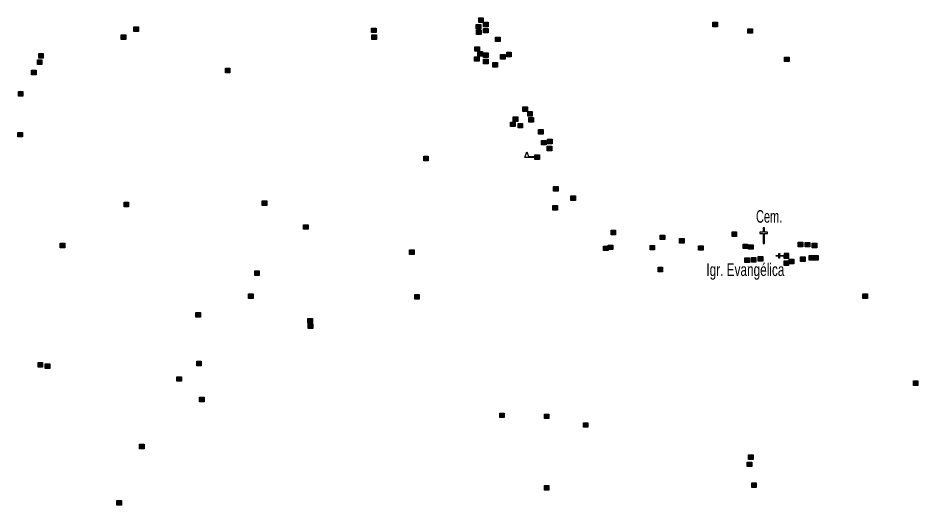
# Model space of a CAD drawing. Extents: x 647.8 to 672.9, y 6929.3 to 6957.3.
# Drawn here: x 654.32 to 660.04, y 6953.98 to 6957.07 of the extents above; entities that cross this region are included whole.
import ezdxf
from ezdxf.enums import TextEntityAlignment as Align

# ---------------------------------------------------------------- set-up
doc = ezdxf.new("R2010")
doc.units = 0
doc.header["$LTSCALE"] = 0.032
for name, color, linetype, lineweight in [('2', 7, 'Continuous', 25), ('20', 7, 'Continuous', 25), ('4', 7, 'Continuous', 25), ('6', 7, 'Continuous', 25)]:
    doc.layers.add(name, color=color, linetype=linetype, lineweight=lineweight)
doc.layers.add('61', color=7, linetype='Continuous')

msp = doc.modelspace()

# ---------------------------------------------------------------- hatches: boundary and pattern name
at = {"layer": '2'}
for points in [[(657.2334, 6957.0283), (657.2624, 6957.0283), (657.2624, 6956.9993), (657.2334, 6956.9993)], [(657.2488, 6957.07), (657.2778, 6957.07), (657.2778, 6957.041), (657.2488, 6957.041)], [(657.2795, 6957.0436), (657.3085, 6957.0436), (657.3085, 6957.0146), (657.2795, 6957.0146)], [(658.7362, 6957.0436), (658.7652, 6957.0436), (658.7652, 6957.0146), (658.7362, 6957.0146)], [(655.0593, 6957.0129), (655.0883, 6957.0129), (655.0883, 6956.9839), (655.0593, 6956.9839)], [(656.5687, 6957.0063), (656.5977, 6957.0063), (656.5977, 6956.9773), (656.5687, 6956.9773)], [(657.2356, 6956.9932), (657.2646, 6956.9932), (657.2646, 6956.9642), (657.2356, 6956.9642)], [(657.2795, 6957.0041), (657.3085, 6957.0041), (657.3085, 6956.9751), (657.2795, 6956.9751)], [(658.9578, 6957.002), (658.9868, 6957.002), (658.9868, 6956.973), (658.9578, 6956.973)], [(654.9803, 6956.9625), (655.0093, 6956.9625), (655.0093, 6956.9335), (654.9803, 6956.9335)], [(656.5709, 6956.9625), (656.5999, 6956.9625), (656.5999, 6956.9335), (656.5709, 6956.9335)], [(657.3563, 6956.9493), (657.3853, 6956.9493), (657.3853, 6956.9203), (657.3563, 6956.9203)], [(657.2246, 6956.8879), (657.2536, 6956.8879), (657.2536, 6956.8589), (657.2246, 6956.8589)], [(657.2444, 6956.8572), (657.2734, 6956.8572), (657.2734, 6956.8282), (657.2444, 6956.8282)], [(657.4265, 6956.8528), (657.4555, 6956.8528), (657.4555, 6956.8238), (657.4265, 6956.8238)], [(654.4472, 6956.8045), (654.4762, 6956.8045), (654.4762, 6956.7755), (654.4472, 6956.7755)], [(654.456, 6956.844), (654.485, 6956.844), (654.485, 6956.815), (654.456, 6956.815)], [(657.2225, 6956.8243), (657.2515, 6956.8243), (657.2515, 6956.7953), (657.2225, 6956.7953)], [(657.2795, 6956.8484), (657.3085, 6956.8484), (657.3085, 6956.8194), (657.2795, 6956.8194)], [(657.2795, 6956.8089), (657.3085, 6956.8089), (657.3085, 6956.7799), (657.2795, 6956.7799)], [(657.387, 6956.8374), (657.416, 6956.8374), (657.416, 6956.8084), (657.387, 6956.8084)], [(659.1903, 6956.8221), (659.2193, 6956.8221), (659.2193, 6956.7931), (659.1903, 6956.7931)], [(654.4099, 6956.7387), (654.4389, 6956.7387), (654.4389, 6956.7097), (654.4099, 6956.7097)], [(655.6407, 6956.7519), (655.6697, 6956.7519), (655.6697, 6956.7229), (655.6407, 6956.7229)], [(657.3387, 6956.787), (657.3677, 6956.787), (657.3677, 6956.758), (657.3387, 6956.758)], [(654.3266, 6956.6027), (654.3556, 6956.6027), (654.3556, 6956.5737), (654.3266, 6956.5737)], [(657.5296, 6956.5061), (657.5586, 6956.5061), (657.5586, 6956.4771), (657.5296, 6956.4771)], [(657.5603, 6956.4754), (657.5893, 6956.4754), (657.5893, 6956.4464), (657.5603, 6956.4464)], [(657.4506, 6956.4096), (657.4796, 6956.4096), (657.4796, 6956.3806), (657.4506, 6956.3806)], [(657.4682, 6956.4425), (657.4972, 6956.4425), (657.4972, 6956.4135), (657.4682, 6956.4135)], [(657.4989, 6956.4008), (657.5279, 6956.4008), (657.5279, 6956.3718), (657.4989, 6956.3718)], [(657.5669, 6956.4381), (657.5959, 6956.4381), (657.5959, 6956.4091), (657.5669, 6956.4091)], [(654.3244, 6956.3438), (654.3534, 6956.3438), (654.3534, 6956.3148), (654.3244, 6956.3148)], [(657.6283, 6956.3614), (657.6573, 6956.3614), (657.6573, 6956.3324), (657.6283, 6956.3324)], [(657.6481, 6956.2933), (657.6771, 6956.2933), (657.6771, 6956.2643), (657.6481, 6956.2643)], [(657.6854, 6956.2999), (657.7144, 6956.2999), (657.7144, 6956.2709), (657.6854, 6956.2709)], [(657.6832, 6956.256), (657.7122, 6956.256), (657.7122, 6956.227), (657.6832, 6956.227)], [(656.9, 6956.1924), (656.929, 6956.1924), (656.929, 6956.1634), (656.9, 6956.1634)], [(657.7248, 6955.9994), (657.7538, 6955.9994), (657.7538, 6955.9704), (657.7248, 6955.9704)], [(657.8345, 6955.9401), (657.8635, 6955.9401), (657.8635, 6955.9111), (657.8345, 6955.9111)], [(654.9979, 6955.9006), (655.0269, 6955.9006), (655.0269, 6955.8716), (654.9979, 6955.8716)], [(655.8754, 6955.9094), (655.9044, 6955.9094), (655.9044, 6955.8804), (655.8754, 6955.8804)], [(657.7205, 6955.8787), (657.7495, 6955.8787), (657.7495, 6955.8497), (657.7205, 6955.8497)], [(656.1365, 6955.758), (656.1655, 6955.758), (656.1655, 6955.729), (656.1365, 6955.729)], [(658.089, 6955.7229), (658.118, 6955.7229), (658.118, 6955.6939), (658.089, 6955.6939)], [(658.8569, 6955.712), (658.8859, 6955.712), (658.8859, 6955.683), (658.8569, 6955.683)], [(658.4005, 6955.6922), (658.4295, 6955.6922), (658.4295, 6955.6632), (658.4005, 6955.6632)], [(658.5234, 6955.6703), (658.5524, 6955.6703), (658.5524, 6955.6413), (658.5234, 6955.6413)], [(654.592, 6955.6396), (654.621, 6955.6396), (654.621, 6955.6106), (654.592, 6955.6106)], [(656.81, 6955.5979), (656.839, 6955.5979), (656.839, 6955.5689), (656.81, 6955.5689)], [(658.0408, 6955.622), (658.0698, 6955.622), (658.0698, 6955.593), (658.0408, 6955.593)], [(658.0715, 6955.6286), (658.1005, 6955.6286), (658.1005, 6955.5996), (658.0715, 6955.5996)], [(658.3369, 6955.6264), (658.3659, 6955.6264), (658.3659, 6955.5974), (658.3369, 6955.5974)], [(658.6441, 6955.6242), (658.6731, 6955.6242), (658.6731, 6955.5952), (658.6441, 6955.5952)], [(658.9271, 6955.6352), (658.9561, 6955.6352), (658.9561, 6955.6062), (658.9271, 6955.6062)], [(658.9622, 6955.6308), (658.9912, 6955.6308), (658.9912, 6955.6018), (658.9622, 6955.6018)], [(659.2774, 6955.6465), (659.3064, 6955.6465), (659.3064, 6955.6175), (659.2774, 6955.6175)], [(659.322, 6955.6456), (659.351, 6955.6456), (659.351, 6955.6166), (659.322, 6955.6166)], [(659.3656, 6955.6396), (659.3946, 6955.6396), (659.3946, 6955.6106), (659.3656, 6955.6106)], [(658.938, 6955.5474), (658.967, 6955.5474), (658.967, 6955.5184), (658.938, 6955.5184)], [(658.9797, 6955.5496), (659.0087, 6955.5496), (659.0087, 6955.5206), (658.9797, 6955.5206)], [(659.0236, 6955.5562), (659.0526, 6955.5562), (659.0526, 6955.5272), (659.0236, 6955.5272)], [(659.2208, 6955.5393), (659.2498, 6955.5393), (659.2498, 6955.5103), (659.2208, 6955.5103)], [(659.2913, 6955.5535), (659.3203, 6955.5535), (659.3203, 6955.5245), (659.2913, 6955.5245)], [(659.3475, 6955.5626), (659.3765, 6955.5626), (659.3765, 6955.5336), (659.3475, 6955.5336)], [(659.3752, 6955.5617), (659.4042, 6955.5617), (659.4042, 6955.5327), (659.3752, 6955.5327)], [(658.3874, 6955.4882), (658.4164, 6955.4882), (658.4164, 6955.4592), (658.3874, 6955.4592)], [(659.1875, 6955.5285), (659.2165, 6955.5285), (659.2165, 6955.4995), (659.1875, 6955.4995)], [(655.8272, 6955.4641), (655.8562, 6955.4641), (655.8562, 6955.4351), (655.8272, 6955.4351)], [(655.7877, 6955.3193), (655.8167, 6955.3193), (655.8167, 6955.2903), (655.7877, 6955.2903)], [(656.8429, 6955.3149), (656.8719, 6955.3149), (656.8719, 6955.2859), (656.8429, 6955.2859)], [(659.6883, 6955.3193), (659.7173, 6955.3193), (659.7173, 6955.2903), (659.6883, 6955.2903)], [(655.4542, 6955.2008), (655.4832, 6955.2008), (655.4832, 6955.1718), (655.4542, 6955.1718)], [(656.165, 6955.1613), (656.194, 6955.1613), (656.194, 6955.1323), (656.165, 6955.1323)], [(656.1672, 6955.1284), (656.1962, 6955.1284), (656.1962, 6955.0994), (656.1672, 6955.0994)], [(654.4516, 6954.8827), (654.4806, 6954.8827), (654.4806, 6954.8537), (654.4516, 6954.8537)], [(654.4977, 6954.8739), (654.5267, 6954.8739), (654.5267, 6954.8449), (654.4977, 6954.8449)], [(655.4586, 6954.8915), (655.4876, 6954.8915), (655.4876, 6954.8625), (655.4586, 6954.8625)], [(655.3336, 6954.7928), (655.3626, 6954.7928), (655.3626, 6954.7638), (655.3336, 6954.7638)], [(660.0086, 6954.7664), (660.0376, 6954.7664), (660.0376, 6954.7374), (660.0086, 6954.7374)], [(655.4762, 6954.6633), (655.5052, 6954.6633), (655.5052, 6954.6343), (655.4762, 6954.6343)], [(657.3826, 6954.5624), (657.4116, 6954.5624), (657.4116, 6954.5334), (657.3826, 6954.5334)], [(657.6656, 6954.5558), (657.6946, 6954.5558), (657.6946, 6954.5268), (657.6656, 6954.5268)], [(657.9135, 6954.501), (657.9425, 6954.501), (657.9425, 6954.472), (657.9135, 6954.472)], [(655.0966, 6954.365), (655.1256, 6954.365), (655.1256, 6954.336), (655.0966, 6954.336)], [(655.0966, 6954.365), (655.1256, 6954.365), (655.1256, 6954.336), (655.0966, 6954.336)], [(658.9622, 6954.2969), (658.9912, 6954.2969), (658.9912, 6954.2679), (658.9622, 6954.2679)], [(658.9534, 6954.2509), (658.9824, 6954.2509), (658.9824, 6954.2219), (658.9534, 6954.2219)], [(658.9819, 6954.1192), (659.0109, 6954.1192), (659.0109, 6954.0902), (658.9819, 6954.0902)], [(657.6656, 6954.1017), (657.6946, 6954.1017), (657.6946, 6954.0727), (657.6656, 6954.0727)], [(654.9518, 6954.0074), (654.9808, 6954.0074), (654.9808, 6953.9784), (654.9518, 6953.9784)]]:
    msp.add_hatch(color=256, dxfattribs=at).paths.add_polyline_path(points)
at = {"layer": '4'}
msp.add_hatch(color=256, dxfattribs=at).paths.add_polyline_path([(657.6348, 6956.1723), (657.6048, 6956.1724), (657.605, 6956.2024), (657.635, 6956.2023)])
at = {"layer": '6'}
for points in [[(659.1869, 6955.5623), (659.1868, 6955.5573), (659.1593, 6955.5575), (659.1592, 6955.545), (659.1542, 6955.5451), (659.1543, 6955.5576), (659.1368, 6955.5578), (659.1369, 6955.5627), (659.1544, 6955.5626), (659.1544, 6955.5751), (659.1595, 6955.575), (659.1594, 6955.5625)], [(659.1868, 6955.5449), (659.2168, 6955.5446), (659.217, 6955.5746), (659.187, 6955.5748)]]:
    msp.add_hatch(color=256, dxfattribs=at).paths.add_polyline_path(points)

# ---------------------------------------------------------------- linework, layer by layer
at = {"layer": '2'}
for points in [[(657.2334, 6957.0283), (657.2624, 6957.0283), (657.2624, 6956.9993), (657.2334, 6956.9993)], [(657.2488, 6957.07), (657.2778, 6957.07), (657.2778, 6957.041), (657.2488, 6957.041)], [(657.2795, 6957.0436), (657.3085, 6957.0436), (657.3085, 6957.0146), (657.2795, 6957.0146)], [(658.7362, 6957.0436), (658.7652, 6957.0436), (658.7652, 6957.0146), (658.7362, 6957.0146)], [(655.0593, 6957.0129), (655.0883, 6957.0129), (655.0883, 6956.9839), (655.0593, 6956.9839)], [(656.5687, 6957.0063), (656.5977, 6957.0063), (656.5977, 6956.9773), (656.5687, 6956.9773)], [(657.2356, 6956.9932), (657.2646, 6956.9932), (657.2646, 6956.9642), (657.2356, 6956.9642)], [(657.2795, 6957.0041), (657.3085, 6957.0041), (657.3085, 6956.9751), (657.2795, 6956.9751)], [(658.9578, 6957.002), (658.9868, 6957.002), (658.9868, 6956.973), (658.9578, 6956.973)], [(654.9803, 6956.9625), (655.0093, 6956.9625), (655.0093, 6956.9335), (654.9803, 6956.9335)], [(656.5709, 6956.9625), (656.5999, 6956.9625), (656.5999, 6956.9335), (656.5709, 6956.9335)], [(657.3563, 6956.9493), (657.3853, 6956.9493), (657.3853, 6956.9203), (657.3563, 6956.9203)], [(657.2246, 6956.8879), (657.2536, 6956.8879), (657.2536, 6956.8589), (657.2246, 6956.8589)], [(657.2444, 6956.8572), (657.2734, 6956.8572), (657.2734, 6956.8282), (657.2444, 6956.8282)], [(657.4265, 6956.8528), (657.4555, 6956.8528), (657.4555, 6956.8238), (657.4265, 6956.8238)], [(654.4472, 6956.8045), (654.4762, 6956.8045), (654.4762, 6956.7755), (654.4472, 6956.7755)], [(654.456, 6956.844), (654.485, 6956.844), (654.485, 6956.815), (654.456, 6956.815)], [(657.2225, 6956.8243), (657.2515, 6956.8243), (657.2515, 6956.7953), (657.2225, 6956.7953)], [(657.2795, 6956.8484), (657.3085, 6956.8484), (657.3085, 6956.8194), (657.2795, 6956.8194)], [(657.2795, 6956.8089), (657.3085, 6956.8089), (657.3085, 6956.7799), (657.2795, 6956.7799)], [(657.387, 6956.8374), (657.416, 6956.8374), (657.416, 6956.8084), (657.387, 6956.8084)], [(659.1903, 6956.8221), (659.2193, 6956.8221), (659.2193, 6956.7931), (659.1903, 6956.7931)], [(654.4099, 6956.7387), (654.4389, 6956.7387), (654.4389, 6956.7097), (654.4099, 6956.7097)], [(655.6407, 6956.7519), (655.6697, 6956.7519), (655.6697, 6956.7229), (655.6407, 6956.7229)], [(657.3387, 6956.787), (657.3677, 6956.787), (657.3677, 6956.758), (657.3387, 6956.758)], [(654.3266, 6956.6027), (654.3556, 6956.6027), (654.3556, 6956.5737), (654.3266, 6956.5737)], [(657.5296, 6956.5061), (657.5586, 6956.5061), (657.5586, 6956.4771), (657.5296, 6956.4771)], [(657.5603, 6956.4754), (657.5893, 6956.4754), (657.5893, 6956.4464), (657.5603, 6956.4464)], [(657.4506, 6956.4096), (657.4796, 6956.4096), (657.4796, 6956.3806), (657.4506, 6956.3806)], [(657.4682, 6956.4425), (657.4972, 6956.4425), (657.4972, 6956.4135), (657.4682, 6956.4135)], [(657.4989, 6956.4008), (657.5279, 6956.4008), (657.5279, 6956.3718), (657.4989, 6956.3718)], [(657.5669, 6956.4381), (657.5959, 6956.4381), (657.5959, 6956.4091), (657.5669, 6956.4091)], [(654.3244, 6956.3438), (654.3534, 6956.3438), (654.3534, 6956.3148), (654.3244, 6956.3148)], [(657.6283, 6956.3614), (657.6573, 6956.3614), (657.6573, 6956.3324), (657.6283, 6956.3324)], [(657.6481, 6956.2933), (657.6771, 6956.2933), (657.6771, 6956.2643), (657.6481, 6956.2643)], [(657.6854, 6956.2999), (657.7144, 6956.2999), (657.7144, 6956.2709), (657.6854, 6956.2709)], [(657.6832, 6956.256), (657.7122, 6956.256), (657.7122, 6956.227), (657.6832, 6956.227)], [(656.9, 6956.1924), (656.929, 6956.1924), (656.929, 6956.1634), (656.9, 6956.1634)], [(657.7248, 6955.9994), (657.7538, 6955.9994), (657.7538, 6955.9704), (657.7248, 6955.9704)], [(657.8345, 6955.9401), (657.8635, 6955.9401), (657.8635, 6955.9111), (657.8345, 6955.9111)], [(654.9979, 6955.9006), (655.0269, 6955.9006), (655.0269, 6955.8716), (654.9979, 6955.8716)], [(655.8754, 6955.9094), (655.9044, 6955.9094), (655.9044, 6955.8804), (655.8754, 6955.8804)], [(657.7205, 6955.8787), (657.7495, 6955.8787), (657.7495, 6955.8497), (657.7205, 6955.8497)], [(656.1365, 6955.758), (656.1655, 6955.758), (656.1655, 6955.729), (656.1365, 6955.729)], [(658.089, 6955.7229), (658.118, 6955.7229), (658.118, 6955.6939), (658.089, 6955.6939)], [(658.8569, 6955.712), (658.8859, 6955.712), (658.8859, 6955.683), (658.8569, 6955.683)], [(658.4005, 6955.6922), (658.4295, 6955.6922), (658.4295, 6955.6632), (658.4005, 6955.6632)], [(658.5234, 6955.6703), (658.5524, 6955.6703), (658.5524, 6955.6413), (658.5234, 6955.6413)], [(654.592, 6955.6396), (654.621, 6955.6396), (654.621, 6955.6106), (654.592, 6955.6106)], [(656.81, 6955.5979), (656.839, 6955.5979), (656.839, 6955.5689), (656.81, 6955.5689)], [(658.0408, 6955.622), (658.0698, 6955.622), (658.0698, 6955.593), (658.0408, 6955.593)], [(658.0715, 6955.6286), (658.1005, 6955.6286), (658.1005, 6955.5996), (658.0715, 6955.5996)], [(658.3369, 6955.6264), (658.3659, 6955.6264), (658.3659, 6955.5974), (658.3369, 6955.5974)], [(658.6441, 6955.6242), (658.6731, 6955.6242), (658.6731, 6955.5952), (658.6441, 6955.5952)], [(658.9271, 6955.6352), (658.9561, 6955.6352), (658.9561, 6955.6062), (658.9271, 6955.6062)], [(658.9622, 6955.6308), (658.9912, 6955.6308), (658.9912, 6955.6018), (658.9622, 6955.6018)], [(659.2774, 6955.6465), (659.3064, 6955.6465), (659.3064, 6955.6175), (659.2774, 6955.6175)], [(659.322, 6955.6456), (659.351, 6955.6456), (659.351, 6955.6166), (659.322, 6955.6166)], [(659.3656, 6955.6396), (659.3946, 6955.6396), (659.3946, 6955.6106), (659.3656, 6955.6106)], [(658.938, 6955.5474), (658.967, 6955.5474), (658.967, 6955.5184), (658.938, 6955.5184)], [(658.9797, 6955.5496), (659.0087, 6955.5496), (659.0087, 6955.5206), (658.9797, 6955.5206)], [(659.0236, 6955.5562), (659.0526, 6955.5562), (659.0526, 6955.5272), (659.0236, 6955.5272)], [(659.2208, 6955.5393), (659.2498, 6955.5393), (659.2498, 6955.5103), (659.2208, 6955.5103)], [(659.2913, 6955.5535), (659.3203, 6955.5535), (659.3203, 6955.5245), (659.2913, 6955.5245)], [(659.3475, 6955.5626), (659.3765, 6955.5626), (659.3765, 6955.5336), (659.3475, 6955.5336)], [(659.3752, 6955.5617), (659.4042, 6955.5617), (659.4042, 6955.5327), (659.3752, 6955.5327)], [(658.3874, 6955.4882), (658.4164, 6955.4882), (658.4164, 6955.4592), (658.3874, 6955.4592)], [(659.1875, 6955.5285), (659.2165, 6955.5285), (659.2165, 6955.4995), (659.1875, 6955.4995)], [(655.8272, 6955.4641), (655.8562, 6955.4641), (655.8562, 6955.4351), (655.8272, 6955.4351)], [(655.7877, 6955.3193), (655.8167, 6955.3193), (655.8167, 6955.2903), (655.7877, 6955.2903)], [(656.8429, 6955.3149), (656.8719, 6955.3149), (656.8719, 6955.2859), (656.8429, 6955.2859)], [(659.6883, 6955.3193), (659.7173, 6955.3193), (659.7173, 6955.2903), (659.6883, 6955.2903)], [(655.4542, 6955.2008), (655.4832, 6955.2008), (655.4832, 6955.1718), (655.4542, 6955.1718)], [(656.165, 6955.1613), (656.194, 6955.1613), (656.194, 6955.1323), (656.165, 6955.1323)], [(656.1672, 6955.1284), (656.1962, 6955.1284), (656.1962, 6955.0994), (656.1672, 6955.0994)], [(654.4516, 6954.8827), (654.4806, 6954.8827), (654.4806, 6954.8537), (654.4516, 6954.8537)], [(654.4977, 6954.8739), (654.5267, 6954.8739), (654.5267, 6954.8449), (654.4977, 6954.8449)], [(655.4586, 6954.8915), (655.4876, 6954.8915), (655.4876, 6954.8625), (655.4586, 6954.8625)], [(655.3336, 6954.7928), (655.3626, 6954.7928), (655.3626, 6954.7638), (655.3336, 6954.7638)], [(660.0086, 6954.7664), (660.0376, 6954.7664), (660.0376, 6954.7374), (660.0086, 6954.7374)], [(655.4762, 6954.6633), (655.5052, 6954.6633), (655.5052, 6954.6343), (655.4762, 6954.6343)], [(657.3826, 6954.5624), (657.4116, 6954.5624), (657.4116, 6954.5334), (657.3826, 6954.5334)], [(657.6656, 6954.5558), (657.6946, 6954.5558), (657.6946, 6954.5268), (657.6656, 6954.5268)], [(657.9135, 6954.501), (657.9425, 6954.501), (657.9425, 6954.472), (657.9135, 6954.472)], [(655.0966, 6954.365), (655.1256, 6954.365), (655.1256, 6954.336), (655.0966, 6954.336)], [(655.0966, 6954.365), (655.1256, 6954.365), (655.1256, 6954.336), (655.0966, 6954.336)], [(658.9622, 6954.2969), (658.9912, 6954.2969), (658.9912, 6954.2679), (658.9622, 6954.2679)], [(658.9534, 6954.2509), (658.9824, 6954.2509), (658.9824, 6954.2219), (658.9534, 6954.2219)], [(658.9819, 6954.1192), (659.0109, 6954.1192), (659.0109, 6954.0902), (658.9819, 6954.0902)], [(657.6656, 6954.1017), (657.6946, 6954.1017), (657.6946, 6954.0727), (657.6656, 6954.0727)], [(654.9518, 6954.0074), (654.9808, 6954.0074), (654.9808, 6953.9784), (654.9518, 6953.9784)]]:
    msp.add_lwpolyline(points, close=True, dxfattribs=at)
at = {"layer": '20'}
for points in [[(659.0545, 6955.7095), (659.0345, 6955.7095), (659.0345, 6955.701), (659.0545, 6955.701), (659.0545, 6955.6375)], [(659.0625, 6955.7095), (659.0625, 6955.7375), (659.0545, 6955.7375), (659.0545, 6955.7095)], [(659.0625, 6955.701), (659.0825, 6955.701), (659.0825, 6955.7095), (659.0625, 6955.7095)], [(659.0545, 6955.6375), (659.0625, 6955.6375), (659.0625, 6955.701)]]:
    msp.add_lwpolyline(points, dxfattribs=at)
at = {"layer": '4'}
msp.add_line((657.6049, 6956.1849), (657.6049, 6956.1899), dxfattribs=at)
for points in [[(657.6049, 6956.1849), (657.5424, 6956.1852), (657.555, 6956.2201), (657.5654, 6956.1901), (657.6049, 6956.1899)], [(657.6348, 6956.1723), (657.6048, 6956.1724), (657.605, 6956.2024), (657.635, 6956.2023)]]:
    msp.add_lwpolyline(points, close=True, dxfattribs=at)
at = {"layer": '6'}
for points in [[(659.1869, 6955.5623), (659.1868, 6955.5573), (659.1593, 6955.5575), (659.1592, 6955.545), (659.1542, 6955.5451), (659.1543, 6955.5576), (659.1368, 6955.5578), (659.1369, 6955.5627), (659.1544, 6955.5626), (659.1544, 6955.5751), (659.1595, 6955.575), (659.1594, 6955.5625)], [(659.1868, 6955.5449), (659.2168, 6955.5446), (659.217, 6955.5746), (659.187, 6955.5748)]]:
    msp.add_lwpolyline(points, close=True, dxfattribs=at)

# ---------------------------------------------------------------- texts
at = {"layer": '61', "width": 0.65}
msp.add_text('Cem.', height=0.08, dxfattribs=at).set_placement((659.0095, 6955.7705))
at = {"layer": '61', "width": 0.7}
msp.add_text('Igr. Evangélica', height=0.08, dxfattribs=at).set_placement((659.1896, 6955.432), align=Align.RIGHT)

doc.saveas('drawing.dxf')
